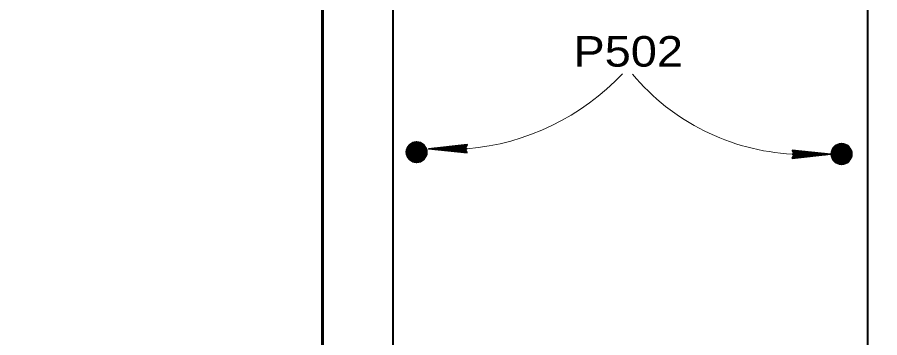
# Model space of a CAD drawing. Extents: x 6.34 to 9.53, y -1.46 to 0.53.
# Drawn here: x 7.7101 to 7.9457, y -0.6375 to -0.5501 of the extents above; entities that cross this region are included whole.
import ezdxf

# ---------------------------------------------------------------- set-up
doc = ezdxf.new("R2010")
doc.units = 0
doc.header["$LTSCALE"] = 0.0033
doc.layers.add('1', color=7, linetype='Continuous', lineweight=40)

msp = doc.modelspace()

# ---------------------------------------------------------------- linework, layer by layer
at = {"layer": '1'}
for p, q in [((7.817083, -0.585333), (7.821667, -0.5875)), ((7.81725, -0.586333), (7.821083, -0.587)), ((7.81725, -0.5865), (7.821083, -0.58725)), ((7.817333, -0.58575), (7.82125, -0.5865)), ((7.817333, -0.585917), (7.82125, -0.586667)), ((7.817333, -0.586167), (7.821167, -0.586917)), ((7.817417, -0.585333), (7.821333, -0.586)), ((7.817417, -0.5855), (7.821333, -0.58625)), ((7.8175, -0.585), (7.821333, -0.585667)), ((7.819417, -0.585833), (7.82075, -0.584833)), ((7.8215, -0.585667), (7.82025, -0.5845)), ((7.933167, -0.585833), (7.93775, -0.588)), ((7.933417, -0.58625), (7.937333, -0.587)), ((7.933417, -0.586417), (7.937333, -0.587167)), ((7.9335, -0.585833), (7.937417, -0.5865)), ((7.9335, -0.586), (7.937417, -0.58675)), ((7.933583, -0.5855), (7.937417, -0.586167)), ((7.9355, -0.586333), (7.936833, -0.585333)), ((7.937583, -0.586167), (7.936333, -0.585)), ((7.816917, -0.588083), (7.82075, -0.588833)), ((7.816917, -0.58825), (7.82075, -0.589)), ((7.817, -0.587583), (7.820917, -0.588333)), ((7.817, -0.58775), (7.820833, -0.5885)), ((7.817, -0.588), (7.820833, -0.588667)), ((7.817083, -0.587167), (7.821, -0.587917)), ((7.817167, -0.58675), (7.821, -0.5875)), ((7.817167, -0.586917), (7.821, -0.587667)), ((7.82125, -0.5885), (7.8175, -0.588917)), ((7.933, -0.588583), (7.936833, -0.589333)), ((7.933, -0.58875), (7.936833, -0.5895)), ((7.933083, -0.588083), (7.937, -0.588833)), ((7.933083, -0.58825), (7.936917, -0.589)), ((7.933083, -0.5885), (7.936917, -0.589167)), ((7.933167, -0.587667), (7.937083, -0.588417)), ((7.93325, -0.58725), (7.937083, -0.588)), ((7.93325, -0.587417), (7.937083, -0.588167)), ((7.933333, -0.586833), (7.937167, -0.5875)), ((7.933333, -0.587), (7.937167, -0.58775)), ((7.933417, -0.586667), (7.93725, -0.587417)), ((7.937333, -0.589), (7.933583, -0.589417))]:
    msp.add_line(p, q, dxfattribs=at)
at = {"layer": '1', "lineweight": 60}
for p, q in [((7.817333, -0.585333), (7.817167, -0.58825)), ((7.817583, -0.585333), (7.817333, -0.58825)), ((7.81775, -0.585333), (7.817583, -0.588333)), ((7.817917, -0.585333), (7.817667, -0.588333)), ((7.818083, -0.585333), (7.817917, -0.588333)), ((7.818333, -0.585333), (7.818167, -0.588333)), ((7.818583, -0.585333), (7.818333, -0.588333)), ((7.818667, -0.585417), (7.8185, -0.588333)), ((7.818833, -0.585417), (7.818667, -0.588333)), ((7.819, -0.585417), (7.818833, -0.588333)), ((7.81925, -0.585417), (7.819, -0.588333)), ((7.819417, -0.585417), (7.81925, -0.588333)), ((7.819667, -0.5855), (7.819417, -0.588417)), ((7.819917, -0.5855), (7.819667, -0.588417)), ((7.820083, -0.5855), (7.819917, -0.588417)), ((7.820167, -0.5855), (7.82, -0.588417)), ((7.820333, -0.5855), (7.820167, -0.588417)), ((7.820417, -0.5855), (7.82025, -0.588417)), ((7.820667, -0.585583), (7.820417, -0.5885)), ((7.820833, -0.585583), (7.820667, -0.5885)), ((7.821, -0.585583), (7.82075, -0.5885)), ((7.821167, -0.585583), (7.821, -0.5885)), ((7.821417, -0.585583), (7.82125, -0.5885)), ((7.821667, -0.5875), (7.8215, -0.585667)), ((7.933417, -0.585833), (7.93325, -0.58875)), ((7.933667, -0.585833), (7.933417, -0.58875)), ((7.933833, -0.585833), (7.933667, -0.588833)), ((7.934, -0.585833), (7.93375, -0.588833)), ((7.934167, -0.585833), (7.934, -0.588833)), ((7.934417, -0.585833), (7.93425, -0.588833)), ((7.934667, -0.585833), (7.934417, -0.588833)), ((7.93475, -0.585917), (7.934583, -0.588833)), ((7.934917, -0.585917), (7.93475, -0.588833)), ((7.935083, -0.585917), (7.934917, -0.588833)), ((7.935333, -0.585917), (7.935083, -0.588833)), ((7.9355, -0.585917), (7.935333, -0.588833)), ((7.93575, -0.586), (7.9355, -0.588917)), ((7.936, -0.586), (7.93575, -0.588917)), ((7.936167, -0.586), (7.936, -0.588917)), ((7.93625, -0.586), (7.936083, -0.588917)), ((7.936417, -0.586), (7.93625, -0.588917)), ((7.9365, -0.586), (7.936333, -0.588917)), ((7.93675, -0.586083), (7.9365, -0.589)), ((7.936917, -0.586083), (7.93675, -0.589)), ((7.937083, -0.586083), (7.936833, -0.589)), ((7.93725, -0.586083), (7.937083, -0.589)), ((7.9375, -0.586083), (7.937333, -0.589)), ((7.93775, -0.588), (7.937583, -0.586167)), ((7.821667, -0.5875), (7.816917, -0.58825)), ((7.93775, -0.588), (7.933, -0.58875))]:
    msp.add_line(p, q, dxfattribs=at)
at = {"layer": '1', "lineweight": 35}
for p, q in [((7.833, -0.586), (7.822417, -0.586)), ((7.83275, -0.586833), (7.824917, -0.585833)), ((7.83275, -0.586833), (7.824917, -0.586)), ((7.83275, -0.587), (7.824917, -0.586083)), ((7.83275, -0.587), (7.824917, -0.586083)), ((7.83275, -0.586917), (7.824917, -0.586083)), ((7.83275, -0.584917), (7.825417, -0.58575)), ((7.83275, -0.585083), (7.825417, -0.585833)), ((7.83275, -0.585167), (7.825417, -0.586)), ((7.832833, -0.585333), (7.8255, -0.586083)), ((7.922, -0.586417), (7.929833, -0.587333)), ((7.922, -0.586417), (7.929833, -0.587333)), ((7.922, -0.5865), (7.929833, -0.587333)), ((7.922, -0.586583), (7.929833, -0.587417)), ((7.922, -0.586583), (7.929833, -0.587583)), ((7.92175, -0.587417), (7.932333, -0.587417)), ((7.921917, -0.588083), (7.92925, -0.587333)), ((7.922, -0.58825), (7.929333, -0.587417)), ((7.922, -0.588333), (7.929333, -0.587583)), ((7.922, -0.5885), (7.929333, -0.587667))]:
    msp.add_line(p, q, dxfattribs=at)
at = {"layer": '1', "lineweight": 60}
for points in [[(7.710083, -0.722833), (7.793417, -0.722833), (7.793417, -0.3895), (7.960083, -0.3895), (7.960083, -0.722833), (8.043417, -0.722833)], [(7.8165, -0.587), (7.821667, -0.586333), (7.817083, -0.585333)], [(7.82075, -0.589), (7.82075, -0.584833), (7.819083, -0.5895), (7.819583, -0.584333), (7.8175, -0.588917), (7.81825, -0.584417), (7.819833, -0.589417), (7.816667, -0.586083), (7.8215, -0.585667), (7.81825, -0.589333), (7.82025, -0.5845), (7.817083, -0.585333), (7.816917, -0.58825)], [(7.8175, -0.588917), (7.819, -0.586667), (7.816833, -0.58575), (7.818833, -0.584333), (7.819, -0.586583), (7.820667, -0.588917), (7.816667, -0.586583), (7.819417, -0.585833)], [(7.82025, -0.5845), (7.819, -0.586667), (7.82125, -0.5885)], [(7.932583, -0.5875), (7.93775, -0.586833), (7.933167, -0.585833)], [(7.936833, -0.5895), (7.936833, -0.585333), (7.935167, -0.59), (7.935667, -0.584833), (7.933583, -0.589417), (7.934333, -0.584917), (7.935917, -0.589917), (7.93275, -0.586583), (7.937583, -0.586167), (7.934333, -0.589833), (7.936333, -0.585), (7.933167, -0.585833), (7.933, -0.58875)], [(7.933583, -0.589417), (7.935083, -0.587167), (7.932917, -0.58625), (7.934917, -0.584833), (7.935083, -0.587083), (7.93675, -0.589417), (7.93275, -0.587083), (7.9355, -0.586333)], [(7.936333, -0.585), (7.935083, -0.587167), (7.937333, -0.589)]]:
    msp.add_lwpolyline(points, dxfattribs=at)
at = {"layer": '1'}
for points in [[(7.818583, -0.410167), (7.818583, -0.458833), (7.812667, -0.46475), (7.812667, -0.673083), (7.818583, -0.679), (7.818583, -0.711417)], [(7.9365, -0.708167), (7.9365, -0.679083), (7.942417, -0.673167), (7.942417, -0.464833), (7.9365, -0.458917), (7.9365, -0.410333)], [(7.816917, -0.58825), (7.819, -0.5895), (7.82075, -0.589), (7.821667, -0.5875)], [(7.933, -0.58875), (7.935083, -0.59), (7.936833, -0.5895), (7.93775, -0.588)]]:
    msp.add_lwpolyline(points, dxfattribs=at)
at = {"layer": '1', "lineweight": 35}
for points in [[(7.833, -0.587083), (7.822417, -0.586), (7.833, -0.584833), (7.832417, -0.586)], [(7.83225, -0.586083), (7.827583, -0.586167), (7.827583, -0.586083), (7.8285, -0.586083), (7.83225, -0.586167), (7.82925, -0.58625), (7.832417, -0.586333), (7.830167, -0.586417), (7.832417, -0.5865), (7.828917, -0.58625), (7.82425, -0.586083), (7.825167, -0.585833), (7.823917, -0.585833), (7.83225, -0.585833), (7.829833, -0.585667), (7.832417, -0.585667), (7.827083, -0.586083), (7.832417, -0.585417)], [(7.92175, -0.586333), (7.932333, -0.587417), (7.92175, -0.588583), (7.922333, -0.587417)], [(7.9225, -0.587333), (7.927167, -0.58725), (7.927167, -0.587333), (7.92625, -0.587333), (7.9225, -0.58725), (7.9255, -0.587167), (7.922333, -0.587083), (7.924583, -0.587), (7.922333, -0.586917), (7.925833, -0.587167), (7.9305, -0.587333), (7.929583, -0.587583), (7.930833, -0.587583), (7.9225, -0.587583), (7.924917, -0.58775), (7.922333, -0.58775), (7.927667, -0.587333), (7.922333, -0.588)]]:
    msp.add_lwpolyline(points, close=True, dxfattribs=at)
for points in [[(7.83225, -0.586083), (7.832667, -0.586833), (7.832417, -0.586583), (7.83225, -0.58625), (7.832, -0.586333), (7.832167, -0.586667), (7.832333, -0.585917), (7.8325, -0.585417), (7.83275, -0.585)], [(7.9225, -0.587333), (7.922083, -0.586583), (7.922333, -0.586833), (7.9225, -0.587167), (7.92275, -0.587083), (7.922583, -0.58675), (7.922417, -0.5875), (7.92225, -0.588), (7.922, -0.588417)]]:
    msp.add_lwpolyline(points, dxfattribs=at)
at = {"layer": '1', "lineweight": 60}
for centre in [(7.819167, -0.5869), (7.93525, -0.5874)]:
    msp.add_circle(centre, 0.00264, dxfattribs=at)
at = {"layer": '1', "lineweight": 13}
for centre, radius, start, end in [((7.827212, -0.519893), 0.06636, 275.00335, 316.58566), ((7.924964, -0.526435), 0.061067, 219.97438, 266.98319)]:
    msp.add_arc(centre, radius, start, end, dxfattribs=at)

# ---------------------------------------------------------------- texts
at = {"layer": '1', "width": 1.15}
msp.add_text('P502', height=0.008333, dxfattribs=at).set_placement((7.862, -0.563583))

doc.saveas('drawing.dxf')
